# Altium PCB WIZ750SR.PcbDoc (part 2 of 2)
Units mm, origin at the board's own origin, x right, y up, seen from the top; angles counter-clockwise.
Board outline 45 x 30 mm, 4 copper layers (Top Layer, Internal Plane 1, Internal Plane 2, Bottom Layer); 93 components, 69 nets, 325 pads, 127 vias.
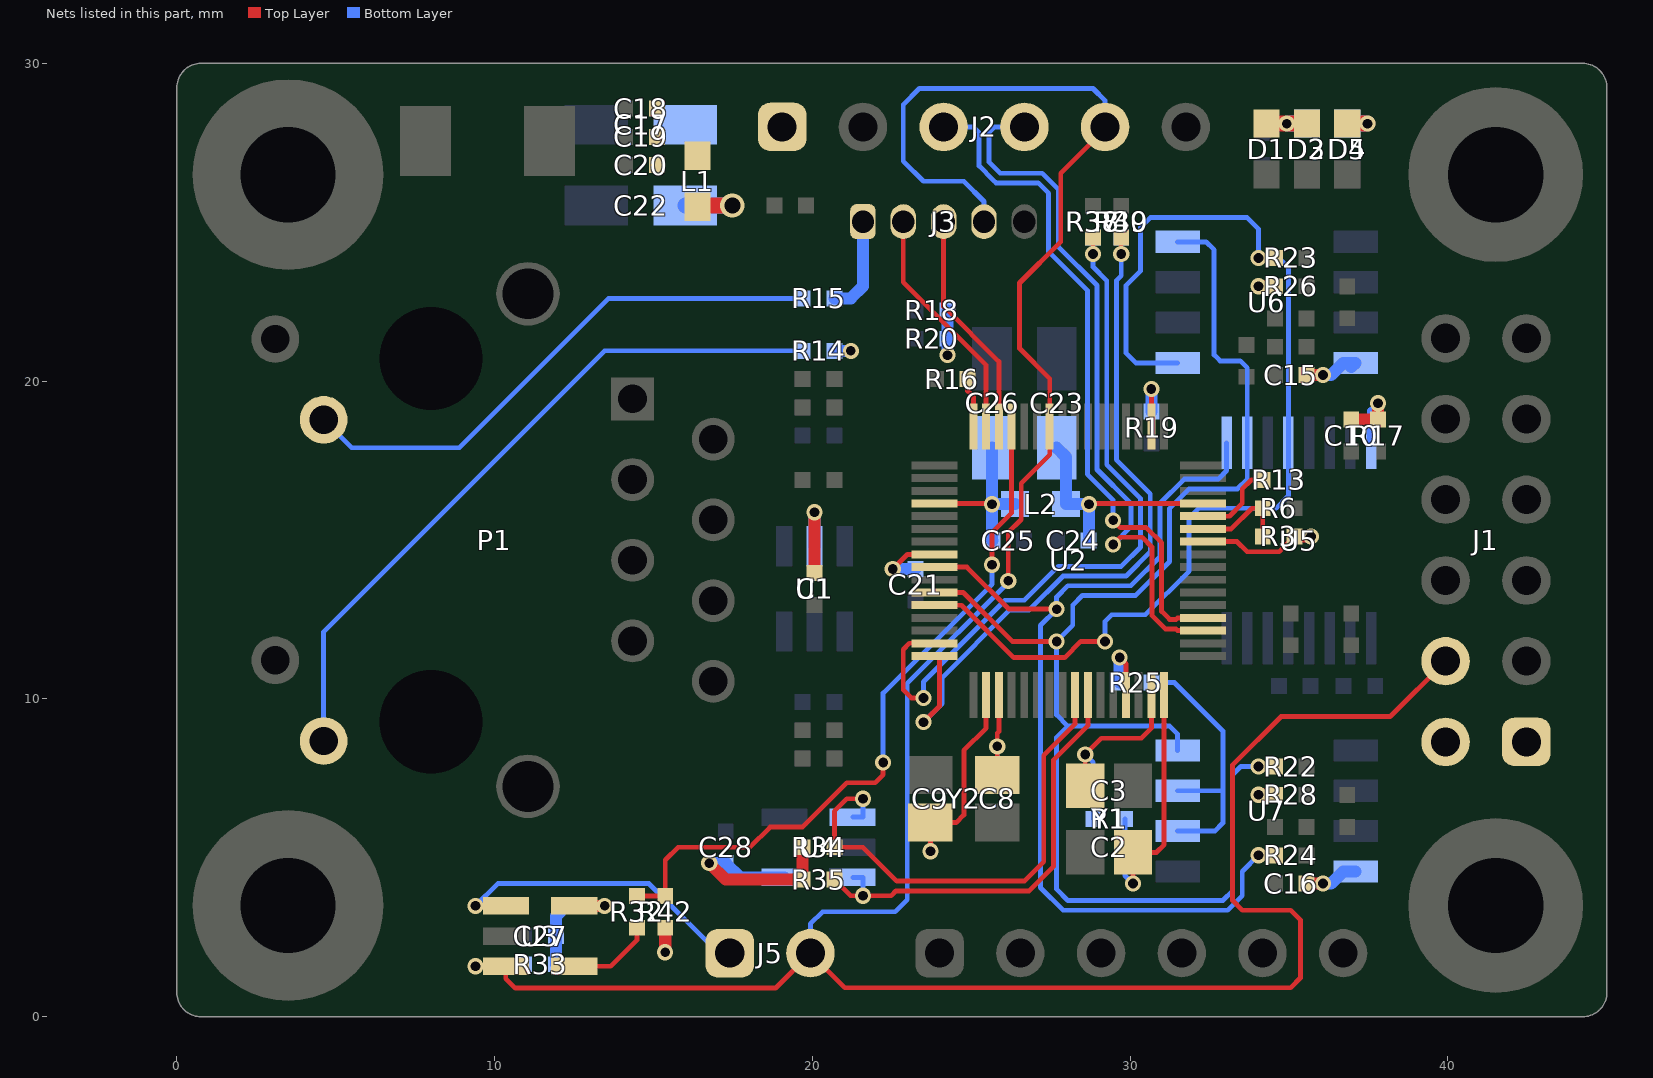
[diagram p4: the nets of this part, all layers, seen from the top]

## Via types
v1: diameter 0.508, hole 0.305, Top Layer to Bottom Layer, tented both sides, 92 vias
v2: diameter 0.762, hole 0.508, Top Layer to Bottom Layer, tented both sides, 35 vias

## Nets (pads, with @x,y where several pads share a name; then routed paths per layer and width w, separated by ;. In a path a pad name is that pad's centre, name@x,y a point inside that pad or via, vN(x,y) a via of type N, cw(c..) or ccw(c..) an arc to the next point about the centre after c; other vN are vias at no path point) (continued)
NetJ5_1: J5.1 U3.1 | length 10.2
  Top Layer w0.152: v1(9.398,3.49) U3.1@10.355,3.49
  Bottom Layer w0.152: v1(9.398,3.49) 10.099,4.191 14.224,4.191 14.859,4.191 17.05,2 J5.1@17.399,2
NetP1_L1: P1.L1 R14.2 | length 22.2
  Bottom Layer w0.152: P1.L1@4.62,8.675 4.62,12.113 13.462,20.955 R14.2@19.693,20.955
NetP1_L3: P1.L3 R15.2 | length 17.4
  Bottom Layer w0.152: P1.L3@4.62,18.785 5.498,17.907 8.89,17.907 13.589,22.606 R15.2@19.693,22.606
NetR13_2: R13.2 U2.12 | length 2.6
  Top Layer w0.152: U2.12@32.292,15.751 33.125,15.751 33.528,16.154 33.528,16.612 33.807,16.891 R13.2@34.171,16.891
NetR16_2: R16.2 U2.32 | length 1.6
  Top Layer w0.152: R16.2@24.884,20.066 24.884,19.693 25.067,19.51 U2.32@25.067,18.576
NetR25_1: R25.1 U7.2 U7.3 | length 8.7
  Bottom Layer w0.152: R25.1@30.675,10.516 31.394,10.516 32.918,8.992 32.918,7.112 ; U7.2@31.49,5.842 32.664,5.842 32.918,6.096 32.918,7.112 ; U7.3@31.49,7.112 32.918,7.112
NetR32_2: R32.2 U3.4 | length 2.9
  Top Layer w0.152: U3.4@12.645,1.45 U3.4@12.505,1.59 13.655,1.59 14.478,2.413 R32.2@14.478,2.802
REGIN: C23.1 C24.2 L2.1 U2.13 | length 7.4
  Top Layer w0.152: v1(28.702,16.129) 28.702,16.151 U2.13@32.292,16.151
  Bottom Layer w0.381: C23.1@27.686,17.904 27.978,17.612 L2.1@27.978,16.129 v1(28.702,16.129) 28.702,14.994 C24.2@28.694,14.986
REGOUT: C25.2 C26.1 L2.2 U2.36 | length 5.5
  Top Layer w0.152: U2.36@23.842,16.151 25.632,16.151 v1(25.654,16.129)
  Bottom Layer w0.381: C26.1@25.654,17.904 v1(25.654,16.129) ; C25.2@25.662,14.986 25.654,14.994 v1(25.654,16.129) ; L2.2@26.378,16.129 v1(25.654,16.129)
"RS232/485 SELECT PIN": R3.1 R6.2 U2.11 | length 3
  Top Layer w0.152: U2.11@32.292,15.351 33.182,15.351 33.833,16.002 R6.2@34.171,16.002 R3.1@34.171,15.113
RSTN: J1.4 J2.5 J3.4 J5.2 R33.1 U2.26 U3.3 | length 90.6
  Top Layer w0.152: v1(9.398,1.59) U3.3@10.355,1.59 10.35,1.585 10.35,1.2 10.65,0.9 18.839,0.9 J5.2@19.939,2 21.025,0.914 35.052,0.914 35.357,1.219 35.357,3.048 35.052,3.353 33.528,3.353 33.223,3.658 33.223,7.925 34.747,9.449 38.185,9.449 J1.4@39.926,11.19 ; v1(26.162,13.716) 26.162,15.24 26.569,15.647 26.569,16.79 27.467,17.688 U2.26@27.467,18.576 27.467,20.082 26.518,21.031 26.518,23.089 27.813,24.384 27.813,26.543 29.21,27.94 J2.5@29.21,28
  Bottom Layer w0.152: v1(9.398,1.59) 10.869,1.59 R33.1@10.93,1.651 ; J5.2@19.939,2 19.939,2.921 20.32,3.302 22.606,3.302 22.987,3.683 22.987,10.49 26.162,13.665 v1(26.162,13.716) ; J3.4@25.4,25.019 25.4,25.654 24.765,26.289 23.495,26.289 22.86,26.924 22.86,28.702 23.368,29.21 28.829,29.21 29.21,28.829 J2.5@29.21,28
RXD_RO: R23.2 U2.44 U5.12 U6.1 | length 34.8
  Top Layer w0.152: U2.44@23.842,12.951 24.692,12.951 26.34,11.303 27.94,11.303 28.448,11.811 v1(29.21,11.811) ; v1(34.036,23.876) R23.2@34.552,23.876
  Bottom Layer w0.152: v1(29.21,11.811) 29.21,12.446 29.413,12.649 30.48,12.649 31.852,14.021 31.852,15.697 32.156,16.002 34.595,16.002 34.981,16.388 U5.12@34.981,18.06 34.981,23.566 34.671,23.876 v1(34.036,23.876) 34.036,24.79 33.68,25.146 30.632,25.146 30.328,24.841 30.328,23.47 29.87,23.012 29.87,20.879 30.175,20.574 U6.1@31.49,20.574
SCL1: R34.1 U2.57 U4.1 | length 16
  Top Layer w0.152: v1(21.59,6.858) 21.082,6.858 20.693,6.469 R34.1@20.693,5.334 21.59,5.334 22.657,4.267 26.67,4.267 27.28,4.877 27.28,8.23 28.267,9.217 U2.57@28.267,10.126
  Bottom Layer w0.152: U4.1@21.268,6.284 21.59,6.284 v1(21.59,6.858)
SDA1: R35.1 U2.58 U4.3 | length 14.3
  Top Layer w0.152: R35.1@20.759,4.384 R35.1@20.693,4.318 21.201,3.81 v1(21.59,3.81) 22.479,3.81 22.631,3.962 26.822,3.962 27.584,4.724 27.584,8.077 28.667,9.16 U2.58@28.667,10.126
  Bottom Layer w0.152: U4.3@21.268,4.384 21.59,4.384 v1(21.59,3.81)
STATUS_LED0: R37.2 R38.2 U2.47 | length 23
  Top Layer w0.152: v1(23.495,10.033) 23.114,10.033 22.86,10.287 22.86,11.557 23.054,11.751 U2.47@23.842,11.751 ; v1(28.829,24.003) R37.2@28.829,24.519
  Bottom Layer w0.152: v1(23.495,10.033) 23.495,10.541 26.06,13.106 26.67,13.106 27.737,14.173 29.718,14.173 30.328,14.783 30.328,16.307 29.261,17.374 29.261,23.165 28.829,23.597 v1(28.829,24.003) R38.2@28.829,24.519
STATUS_LED1: R39.2 R40.2 U2.48 | length 23.2
  Top Layer w0.152: v1(23.495,9.271) 24.003,9.779 24.003,11.351 U2.48@23.842,11.351 ; v1(29.718,24.003) R39.2@29.718,24.519
  Bottom Layer w0.152: v1(23.495,9.271) 24.079,9.855 24.079,10.668 26.213,12.802 26.822,12.802 27.889,13.868 29.87,13.868 30.632,14.63 30.632,16.459 29.566,17.526 29.566,23.165 29.718,23.317 v1(29.718,24.003) R40.2@29.718,24.519
SWCLK: J3.3 U2.30 | length 7.2
  Top Layer w0.152: J3.3@24.13,25.019 24.13,22.352 25.867,20.615 U2.30@25.867,18.576
SWDIO: J3.2 U2.31 | length 7.5
  Top Layer w0.152: J3.2@22.86,25.019 22.86,23.114 25.467,20.507 U2.31@25.467,18.576
TXD_DI: R22.2 U2.43 U5.10 U6.4 U7.4 | length 46.3
  Top Layer w0.152: U2.43@23.842,13.351 24.749,13.351 26.289,11.811 v1(27.686,11.811) ; v1(34.036,7.874) R22.2@34.552,7.874
  Bottom Layer w0.152: U7.4@31.49,8.382 31.49,8.896 31.242,9.144 28.042,9.144 ; U6.4@31.49,24.384 32.385,24.384 32.639,24.13 32.639,20.828 32.829,20.637 33.465,20.637 33.681,20.421 U5.10@33.681,18.06 33.681,16.917 33.376,16.612 31.852,16.612 31.242,16.002 31.242,14.326 30.175,13.259 28.499,13.259 28.194,12.954 28.194,12.319 v1(27.686,11.811) 27.686,9.5 28.042,9.144 ; v1(34.036,7.874) 33.477,7.874 33.223,7.62 33.223,3.962 32.918,3.658 28.042,3.658 27.686,4.013 27.686,8.788 28.042,9.144
U_CTS0: R24.2 U2.41 U5.9 | length 31.4
  Top Layer w0.152: U2.41@23.842,14.151 24.863,14.151 26.187,12.827 v1(27.686,12.827) ; v1(34.036,5.08) R24.2@34.552,5.08
  Bottom Layer w0.152: U5.9@33.031,18.06 33.031,17.181 32.766,16.916 31.699,16.916 30.937,16.154 30.937,14.478 30.023,13.564 28.042,13.564 27.686,13.208 v1(27.686,12.827) 27.178,12.319 27.178,4.064 27.889,3.353 33.071,3.353 33.528,3.81 33.528,4.572 v1(34.036,5.08)
U_RXD2: J2.3 U2.4 | length 21.3
  Top Layer w0.152: v1(29.464,15.621) 29.693,15.392 30.505,15.392 30.988,14.909 30.988,12.757 31.242,12.503 31.443,12.503 31.491,12.551 U2.4@32.292,12.551
  Bottom Layer w0.152: J2.3@24.13,28 25.061,28 25.248,27.813 25.248,26.772 25.692,26.327 25.782,26.238 27.102,26.238 27.432,25.908 27.432,24.079 28.651,22.86 28.651,17.069 29.464,16.256 v1(29.464,15.621)
U_TXD2: J2.4 U2.3 | length 22.4
  Top Layer w0.152: v1(29.464,14.859) 29.693,15.088 30.378,15.088 30.683,14.783 30.683,12.631 31.116,12.199 31.443,12.199 31.491,12.151 U2.3@32.292,12.151
  Bottom Layer w0.152: J2.4@26.67,28 25.739,28 25.552,27.813 25.552,26.899 25.908,26.543 27.228,26.543 27.737,26.034 27.737,24.232 28.956,23.012 28.956,17.221 30.023,16.154 30.023,15.418 v1(29.464,14.859)
VDD_3.3A: C21.2 C22.1 L1.2 U2.40 | length 4.8
  Top Layer w0.152: v1(22.53,14.089) 22.992,14.551 U2.40@23.842,14.551
  Top Layer w0.508: L1.2@16.383,25.489 16.421,25.527 v2(17.481,25.527)
  Bottom Layer w0.381: v1(22.53,14.089) C21.2@23.241,14.089
  Bottom Layer w0.508: C22.1@16.005,25.527 v2(17.481,25.527)
VDD_3.3V: C1.2 C10.2 C15.2 C16.2 C17.1 C18.2 C19.2 C20.2 C27.2 C28.2 D1.1 D2.1 D3.1 D4.1 D5.1 J1.1 J1.2 J2.1 J3.1 L1.1 R3.2 R14.1 R15.1 R17.1 R18.2 R19.2 R20.2 R25.2 R26.1 R28.1 R33.2 R34.2 R35.2 R42.1 U1.5 U2.10 U2.18 U2.61 U3.5 U4.4 U5.16 U6.8 U7.8 | length 37.4
  Top Layer w0.152: v1(29.667,11.303) 29.867,11.103 U2.61@29.867,10.126 ; U2.18@30.667,18.576 v1(30.667,19.753) ; U2.10@32.292,14.951 33.36,14.951 33.68,14.63 34.688,14.63 R3.2@35.171,15.113
  Top Layer w0.381: U3.5@12.505,3.49 v1(13.462,3.49) ; v1(15.367,2.032) 15.371,2.036 R42.1@15.371,2.802 ; v1(16.756,4.834) 17.272,4.318 R35.2@19.693,4.318 R34.2@19.693,5.334 ; C1.2@20.066,13.962 v1(20.066,15.875) ; v1(34.036,6.985) R28.1@34.552,6.985 ; v1(34.036,22.987) R26.1@34.552,22.987 ; R3.2@35.171,15.113 v1(35.687,15.113) ; C16.2@35.552,4.191 v1(36.068,4.191) ; C15.2@35.552,20.193 v1(36.068,20.193) ; C10.2@36.957,18.788 R17.1@37.795,18.788 v1(37.795,19.304)
  Top Layer w0.508: D1.1@34.29,28.105 v1(34.925,28.105) D2.1@35.56,28.105 ; D4.1@36.83,28.105 v1(37.465,28.105)
  Bottom Layer w0.254: U5.16@37.581,18.06 37.581,19.061
  Bottom Layer w0.381: R33.2@11.93,1.651 C27.2@11.93,2.54 11.93,3.167 12.253,3.49 v1(13.462,3.49) ; v1(16.756,4.834) C28.2@17.272,4.834 17.722,4.384 U4.4@19.118,4.384 ; U1.5@20.066,14.802 v1(20.066,15.875) ; R14.1@20.693,20.955 v1(21.209,20.955) ; R15.1@20.693,22.606 21.209,22.606 21.59,22.987 J3.1@21.59,25.019 ; v1(24.249,20.82) R20.2@24.249,21.336 R18.2@24.249,22.225 ; R25.2@29.667,10.524 v1(29.667,11.303) ; R19.2@30.67,19.042 v1@30.67,19.75 ; v1(36.068,4.191) 36.322,4.191 36.703,4.572 U7.8@37.09,4.572 ; v1(36.068,20.193) 36.322,20.193 36.703,20.574 U6.8@37.09,20.574 U6.8@36.957,20.441
  Bottom Layer w0.508: v1(34.925,28.105) D3.1@35.56,28.105 ; D5.1@36.83,28.105 v1(37.465,28.105)
WDI: R32.1 R42.2 U2.29 | length 22.6
  Top Layer w0.152: R32.1@14.478,3.802 R42.2@15.371,3.802 15.371,4.933 15.772,5.334 18.034,5.334 18.669,5.969 19.685,5.969 21.082,7.366 21.971,7.366 22.225,7.62 v1(22.225,8.001) ; v1(25.654,14.224) 25.654,15.24 26.267,15.853 U2.29@26.267,18.576
  Bottom Layer w0.152: v1(22.225,8.001) 22.225,10.185 25.654,13.614 v1(25.654,14.224)
X1: C9.2 U2.50 Y2.3 | length 7.3
  Top Layer w0.152: v1(23.715,5.207) Y2.3@23.715,6.108 24.523,6.108 24.765,6.35 24.765,8.382 25.467,9.084 U2.50@25.467,10.126
  Bottom Layer w0.152: v1(23.715,5.207) C9.2@23.715,6.358
X2: C8.2 U2.51 Y2.1 | length 3.7
  Top Layer w0.152: Y2.1@25.815,7.608 v1(25.815,8.509) 25.815,8.924 25.867,8.976 U2.51@25.867,10.126
  Bottom Layer w0.152: C8.2@25.815,7.358 v1(25.815,8.509)
XIN: C3.2 R1.2 U2.63 Y1.3 | length 6.6
  Top Layer w0.152: Y1.3@28.587,7.273 v1(28.587,8.255) 29.095,8.763 30.353,8.763 30.667,9.077 U2.63@30.667,10.126
  Bottom Layer w0.152: v1(28.587,8.255) 28.837,8.005 C3.2@28.837,7.112 R1.2@28.837,6.223
XOUT: C2.2 R1.1 U2.64 Y1.1 | length 8.9
  Top Layer w0.152: v1(30.087,4.191) Y1.1@30.087,5.173 30.827,5.173 31.067,5.413 U2.64@31.067,10.126
  Bottom Layer w0.152: R1.1@29.837,6.223 C2.2@29.837,5.334 29.837,4.441 v1(30.087,4.191)
pads on no net: P1. P1.R4 P1.R5 P1.R6 U2.8 U2.19 U2.20 U2.21 U2.22 U2.27 U2.45 U2.46 U2.53 U2.54 U2.55 U2.56 U2.59 U2.60 U7.1
copper on no net:
  other v2: 41.5,1.417 40.027,2.027 42.973,2.027 39.417,3.5 43.583,3.5 40.027,4.973 42.973,4.973 41.5,5.583 41.5,24.417 40.027,25.027 42.973,25.027 39.417,26.5 43.583,26.5 40.027,27.973 42.973,27.973 41.5,28.583

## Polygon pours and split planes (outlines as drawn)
VDD_3.3V on Top Layer "Top Layer-net" (solid, remove dead copper, pour order 2): 14.859,26.543 19.812,26.543 20.066,26.797 20.066,29.21 19.812,29.464 19.05,29.464 15.113,29.464 14.859,29.21 14.859,26.543
CH_GND on Top Layer "Top Layer-net" (solid, remove dead copper, pour order 12): 0.762,29.591 0.381,29.21 0.381,27.432 0.381,0.762 0.762,0.381 2.413,0.381 6.198,0.381 6.604,0.787 6.604,1.143 6.604,5.588 6.985,5.969 8.128,5.969 11.938,5.969 12.192,6.223 12.192,23.749 11.938,24.003 9.017,24.003 8.636,24.384 8.636,29.058 8.103,29.591
GND on Top Layer "Top Layer-gnd" (solid, remove dead copper, pour order 16): 11.176,29.591 10.922,29.337 10.922,28.448 10.922,25.527 11.176,25.273 11.811,25.273 12.827,25.273 13.462,24.638 14.605,23.495 18.288,23.495 19.177,23.495 19.431,23.241 19.431,22.987 19.431,6.731 19.177,6.477 18.415,6.477 14.605,6.477 12.954,4.826 8.763,4.826 8.509,4.572 8.509,4.318 8.509,0.635 8.763,0.381 9.652,0.381 37.211,0.381 37.465,0.635 37.465,0.889 37.465,5.461 39.243,7.239 39.624,7.62 42.799,7.62 44.323,7.62 44.577,7.874 44.577,8.509 44.577,22.098 44.323,22.352 44.069,22.352 39.624,22.352 37.465,24.511 37.465,28.575 37.465,29.337 37.211,29.591
GND on Bottom Layer "Top Layer-gnd" (solid, remove dead copper, pour order 22): 11.049,29.464 10.922,29.337 10.922,28.448 10.922,25.527 11.176,25.273 11.811,25.273 12.827,25.273 13.462,24.638 14.605,23.495 18.288,23.495 19.177,23.495 19.431,23.241 19.431,22.987 19.431,6.731 19.177,6.477 18.415,6.477 14.605,6.477 12.827,4.699 8.636,4.699 8.509,4.572 8.509,4.318 8.509,0.635 8.763,0.381 9.652,0.381 37.211,0.381 37.465,0.635 37.465,0.889 37.465,5.461 39.243,7.239 39.624,7.62 42.799,7.62 44.323,7.62 44.577,7.874 44.577,8.509 44.577,22.098 44.323,22.352 44.069,22.352 39.624,22.352 37.465,24.511 37.465,28.575 37.465,29.337 37.338,29.464
CH_GND on Bottom Layer "Top Layer-net" (solid, remove dead copper, pour order 20): 0.762,29.591 0.381,29.21 0.381,27.432 0.381,0.762 0.762,0.381 2.413,0.381 6.198,0.381 6.604,0.787 6.604,1.143 6.604,5.588 6.985,5.969 8.128,5.969 11.938,5.969 12.192,6.223 12.192,23.749 11.938,24.003 9.017,24.003 8.636,24.384 8.636,29.058 8.103,29.591
VDD_3.3V on Bottom Layer "Top Layer-net" (solid, remove dead copper, pour order 6): 16.256,28.829 15.113,28.829 14.859,28.575 14.859,27.559 14.859,27.305 15.113,27.051 16.002,27.051 19.812,27.051 20.066,27.305 20.066,28.575 19.812,28.829
GND on Internal Plane 1 (split plane): 44.304,29.483 44.365,29.458 44.417,29.417 44.458,29.365 44.483,29.304 44.49,29.247 44.49,29.238 44.49,24.044 44.133,23.687 40.212,23.687 38.673,25.226 38.673,29.207 38.956,29.49 44.238,29.49 44.247,29.49
CH_GND on Internal Plane 1 (split plane): 44.49,6.157 44.49,0.762 44.49,0.753 44.483,0.696 44.458,0.635 44.417,0.583 44.365,0.542 44.304,0.517 44.247,0.51 44.238,0.51 38.953,0.51 38.673,0.791 38.673,4.746 40.339,6.412 44.235,6.412
GND on Internal Plane 1 (split plane): 38.289,29.209 38.289,25.146 38.295,25.096 38.307,25.069 38.315,25.05 38.345,25.01 39.996,23.359 40.036,23.329 40.082,23.309 40.132,23.303 44.133,23.303 44.49,22.946 44.49,7.051 44.235,6.796 40.259,6.796 40.209,6.79 40.163,6.77 40.123,6.74 38.345,4.962 38.315,4.922 38.307,4.903 38.295,4.876 38.289,4.826 38.289,0.889 38.289,0.791 38.009,0.51 8.56,0.51 8.56,4.496 8.738,4.674 12.802,4.674 14.173,6.045 14.605,6.477 18.745,6.477 18.745,22.86 15.215,22.86 12.802,25.273 12.273,25.273 11.125,25.273 10.82,25.578 10.82,29.489 9.441,29.489 9.441,29.49 38.009,29.49
CH_GND on Internal Plane 1 (split plane): 0.762,29.49 8.341,29.49 8.558,29.273 8.636,29.195 8.636,25.527 8.637,25.273 8.636,24.383 9.017,24.003 11.938,24.003 12.192,23.749 12.191,6.298 11.862,5.969 6.909,5.969 6.553,5.613 6.553,0.678 6.386,0.51 0.762,0.51 0.753,0.51 0.696,0.517 0.635,0.542 0.583,0.583 0.542,0.635 0.517,0.696 0.51,0.753 0.51,0.762 0.51,29.238 0.51,29.247 0.517,29.304 0.542,29.365 0.583,29.417 0.635,29.458 0.696,29.483 0.753,29.49
VDD_3.3V on Internal Plane 2 (split plane): 44.304,29.483 44.365,29.458 44.417,29.417 44.458,29.365 44.483,29.304 44.49,29.247 44.49,29.238 44.49,24.035 44.142,23.687 40.212,23.687 38.673,25.226 38.673,29.209 38.953,29.49 44.238,29.49 44.247,29.49
VDD_3.3A on Internal Plane 2 (split plane): 14.489,29.311 14.489,26.645 14.496,26.595 14.507,26.568 14.515,26.549 14.545,26.509 14.825,26.229 14.865,26.199 14.911,26.18 14.961,26.173 20.237,26.173 20.509,25.901 20.509,17.174 20.418,17.083 19.939,17.083 19.889,17.077 19.843,17.057 19.803,17.027 19.549,16.773 19.519,16.733 19.511,16.714 19.499,16.687 19.493,16.637 19.493,15.037 19.499,14.987 19.511,14.96 19.519,14.941 19.549,14.901 19.854,14.596 19.894,14.566 19.913,14.558 19.94,14.546 19.99,14.54 23.034,14.54 23.176,14.398 23.176,12.754 23.06,12.638 18.72,12.638 18.72,18.009 19.406,18.009 19.406,20.345 18.72,20.345 18.72,22.835 15.24,22.835 12.802,25.273 12.273,25.273 11.125,25.273 10.82,25.578 10.82,29.489 9.441,29.489 9.441,29.49 14.31,29.49
CH_GND on Internal Plane 2 (split plane): 44.49,6.14 44.49,0.762 44.49,0.753 44.483,0.696 44.458,0.635 44.417,0.583 44.365,0.542 44.304,0.517 44.247,0.51 44.238,0.51 38.953,0.51 38.673,0.791 38.673,4.746 40.339,6.412 44.218,6.412
VDD_3.3V on Internal Plane 2 (split plane): 38.289,29.207 38.289,25.146 38.295,25.096 38.307,25.069 38.315,25.05 38.345,25.01 39.996,23.359 40.036,23.329 40.082,23.309 40.132,23.303 44.133,23.303 44.49,22.946 44.49,7.051 44.235,6.796 40.259,6.796 40.209,6.79 40.163,6.77 40.123,6.74 38.345,4.962 38.315,4.922 38.307,4.903 38.295,4.876 38.289,4.826 38.289,0.791 38.009,0.51 8.56,0.51 8.56,4.496 8.738,4.674 12.802,4.674 14.173,6.045 14.605,6.477 18.72,6.477 18.72,12.254 23.139,12.254 23.189,12.26 23.216,12.272 23.235,12.28 23.275,12.31 23.504,12.539 23.534,12.579 23.554,12.625 23.56,12.675 23.56,14.478 23.554,14.528 23.534,14.574 23.504,14.614 23.25,14.868 23.21,14.898 23.191,14.906 23.164,14.918 23.114,14.924 20.069,14.924 19.877,15.116 19.877,16.557 20.019,16.699 20.498,16.699 20.548,16.705 20.575,16.717 20.594,16.725 20.634,16.755 20.837,16.958 20.867,16.998 20.887,17.044 20.893,17.094 20.893,25.981 20.887,26.031 20.875,26.058 20.867,26.077 20.837,26.117 20.453,26.501 20.413,26.532 20.394,26.54 20.366,26.551 20.317,26.557 15.04,26.557 14.873,26.724 14.873,29.308 15.055,29.49 38.006,29.49
CH_GND on Internal Plane 2 (split plane): 0.762,29.49 8.341,29.49 8.509,29.322 8.636,29.195 8.636,25.527 8.637,25.273 8.636,24.383 9.017,24.003 11.938,24.003 12.192,23.749 12.191,6.298 11.862,5.969 6.909,5.969 6.553,5.613 6.553,0.678 6.386,0.51 0.762,0.51 0.753,0.51 0.696,0.517 0.635,0.542 0.583,0.583 0.542,0.635 0.517,0.696 0.51,0.753 0.51,0.762 0.51,29.238 0.51,29.247 0.517,29.304 0.542,29.365 0.583,29.417 0.635,29.458 0.696,29.483 0.753,29.49

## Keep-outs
Keep-Out Layer:
  the board outline again, w0.127
  text ".Layer_Name" at 9.398,31.75 h1.52

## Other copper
Top Layer:
  pour cut-out: 42.164,12.141 42.164,12.725 42.367,12.725 42.367,12.141
  pour cut-out: 40.843,13.31 41.097,13.564 41.3,13.564 41.554,13.31 41.554,14.173 40.843,14.173
  pour cut-out: 12.191,6.298 12.192,23.749 11.938,24.003 9.017,24.003 8.636,24.383 8.637,25.273 8.636,25.527 8.636,29.489 10.82,29.489 10.82,25.578 11.125,25.273 12.273,25.273 12.802,25.273 15.215,22.86 18.745,22.86 18.745,6.477 14.605,6.477 14.173,6.045 12.802,4.674 8.738,4.674 8.56,4.496 8.56,0.483 6.553,0.483 6.553,5.613 6.909,5.969 11.862,5.969
  pour cut-out: 14.63,29.206 14.122,29.206 14.227,29.31 14.227,29.461 13.997,29.691 13.741,29.691 13.741,30 14.63,30
  pour cut-out: 18.161,6.477 18.39,6.477 18.39,6.121 18.161,6.121 18.263,6.223 18.263,6.375
  pour cut-out: 10.033,1.016 10.312,1.016 10.312,0.381 10.033,0.381 10.033,0.432 10.109,0.508 10.109,0.711 10.033,0.787
  pour cut-out: 14.681,4.394 14.935,4.648 14.935,4.394
  pour cut-out: 22.784,17.475 22.631,17.628 22.784,17.628
  pour cut-out: 21.272,18.567 21.45,18.567 21.806,18.567 21.806,18.237 21.667,18.237 21.632,18.272 21.632,18.449 21.552,18.53 21.32,18.53
  pour cut-out: 21.996,8.966 22.225,8.966 22.327,8.865 22.708,8.865 22.809,8.966 22.809,9.677 22.657,9.83 22.809,9.83 23.05,9.83 23.05,9.207 23.393,8.865 23.393,8.458 21.996,8.458
  text ".Layer_Name" at 9.398,31.75 h1.52
Bottom Layer:
  pour cut-out: 22.047,16.358 22.098,16.358 22.327,16.586 21.869,17.221 21.717,17.069 21.361,17.069
  pour cut-out: 24.181,13.056 24.181,16.866 23.444,17.602 23.444,18.339 23.216,18.11 23.012,18.11 22.835,18.288 22.835,18.009 22.835,17.45 23.698,16.586 23.673,16.561 23.673,15.545 22.962,14.834 22.962,14.63 23.825,14.63 23.825,13.056
  pour cut-out: 12.191,6.298 12.192,23.749 11.938,24.003 9.017,24.003 8.636,24.383 8.637,25.273 8.636,25.527 8.636,29.489 10.82,29.489 10.82,25.578 11.125,25.273 12.273,25.273 12.802,25.273 15.215,22.86 18.745,22.86 18.745,6.477 14.605,6.477 14.173,6.045 12.802,4.674 8.738,4.674 8.56,4.496 8.56,0.483 6.553,0.483 6.553,5.613 6.909,5.969 11.862,5.969
  pour cut-out: 21.692,20.371 22.098,20.371 21.869,20.599 21.869,20.752 21.869,20.98 22.073,21.184 21.692,21.184
  pour cut-out: 22.504,21.158 22.657,21.006 22.657,21.158
  pour cut-out: 32.537,17.526 32.334,17.323 32.537,17.323
  pour cut-out: 33.267,19.402 33.064,19.199 33.267,19.199
  text ".Layer_Name" at 9.398,31.75 h1.52
Internal Plane 1 (plane layer: these items are gaps in the copper):
  pour cut-out: 12.191,6.298 12.192,23.749 11.938,24.003 9.017,24.003 8.636,24.383 8.637,25.273 8.636,25.527 8.636,29.489 10.82,29.489 10.82,25.578 11.125,25.273 12.273,25.273 12.802,25.273 15.215,22.86 18.745,22.86 18.745,6.477 14.605,6.477 14.173,6.045 12.802,4.674 8.738,4.674 8.56,4.496 8.56,0.483 6.553,0.483 6.553,5.613 6.909,5.969 11.862,5.969
  lines w0.381: 6.147,0 6.833,0.686 6.858,0.686 ; 7.544,0 6.858,0.686 ; 8.103,29.997 8.105,29.997 8.301,29.801 8.694,29.409 8.89,29.213 ; 8.891,29.483 9.163,29.483 ; 9.68,30 8.89,29.21 8.89,24.638 9.271,24.257 12.04,24.257 12.446,23.851 12.446,6.096 12.065,5.715 7.214,5.715 6.858,5.359 6.858,0.686 ; 37.77,0 38.481,0.711 ; 37.821,30 37.821,29.949 38.481,29.289 38.481,29.314 ; 38.481,0 38.481,0.889 ; 39.192,0 38.481,0.711 ; 39.192,29.997 38.481,29.286 38.481,25.146 40.132,23.495 44.213,23.495 ; 45,6.604 44.314,6.604 ; 45,7.29 44.314,6.604 ; 45,22.708 44.213,23.495 ; 45,23.495 44.213,23.495 ; 45,24.282 44.213,23.495 ; 45.004,5.914 44.314,6.604 ; 38.481,0.711 38.481,4.826 40.259,6.604 44.314,6.604
  text "GND" at 9.398,31.782 h1.52
Internal Plane 2 (plane layer: these items are gaps in the copper):
  pour cut-out: 18.694,18.009 19.406,18.009 19.406,20.345 18.694,20.345
  pour cut-out: 12.191,6.298 12.192,23.749 11.938,24.003 9.017,24.003 8.636,24.383 8.637,25.273 8.636,25.527 8.636,29.489 10.82,29.489 10.82,25.578 11.125,25.273 12.273,25.273 12.802,25.273 15.24,22.835 18.72,22.835 18.72,6.477 14.605,6.477 14.173,6.045 12.802,4.674 8.738,4.674 8.56,4.496 8.56,0.483 6.553,0.483 6.553,5.613 6.909,5.969 11.862,5.969
  lines w0.381: 6.248,0.102 6.833,0.686 6.858,0.686 ; 7.544,0 6.858,0.686 ; 9.169,29.489 9.138,29.458 8.645,29.458 8.103,30 8.89,29.213 ; 14.072,30 14.681,29.39 14.681,29.388 ; 15.596,30 15.293,30 14.681,29.388 ; 18.415,12.446 23.139,12.446 23.368,12.675 23.368,14.478 23.114,14.732 19.99,14.732 19.685,15.037 19.685,16.637 19.939,16.891 20.498,16.891 20.701,17.094 20.701,25.981 20.317,26.365 14.961,26.365 14.681,26.645 14.681,29.388 ; 38.481,0 37.77,0 38.481,0.711 ; 38.481,30.013 38.783,30.013 ; 39.192,0 38.481,0.711 ; 39.192,30 38.481,29.289 38.481,29.286 ; 44.975,23.495 44.221,23.495 ; 45,6.604 45,7.29 44.314,6.604 44.298,6.604 ; 45,22.708 44.213,23.495 ; 45.004,5.897 44.298,6.604 ; 45.004,24.278 44.221,23.495 ; 6.858,0.686 6.858,5.359 7.214,5.715 12.065,5.715 12.446,6.096 12.446,23.851 12.04,24.257 9.271,24.257 8.89,24.638 8.89,29.21 ; 8.89,29.21 9.68,30 37.767,30 38.481,29.286 ; 8.89,29.21 8.89,29.213 ; 8.89,29.21 8.89,29.213 ; 38.481,0.711 38.481,4.826 40.259,6.604 44.298,6.604 ; 38.481,29.286 38.481,25.146 40.132,23.495 44.213,23.495 ; 44.213,23.495 44.221,23.495
  text "POWER" at 9.398,31.782 h1.52

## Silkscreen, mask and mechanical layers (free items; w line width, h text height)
Top Overlay:
  text ".Layer_Name" at 9.398,31.782 h1.52
  text "WIZ750SR Ver1.1" at 6.604,5.334 h1.52
Bottom Overlay:
  lines w0.203: 24.003,2 24.003,3.238 26.67,3.238 ; 28.829,3.238 31.623,3.238 31.623,2
  text ".Layer_Name" at 9.398,31.75 h1.52
  text "VDD" at 19.812,28.956 h0.64
  text "BOOT" at 22.606,28.956 h0.64
  text "RX" at 24.638,28.956 h0.64
  text "TX" at 27.178,28.956 h0.64
  text "nRST" at 30.226,28.956 h0.64
  text "GND" at 32.512,28.956 h0.64
  text "JTAG" at 25.253,25.961 h0.64
  text "GND" at 42.037,19.812 h0.64
  text "485_SEL" at 41.783,17.272 h0.64
  text "CTS" at 43.688,17.272 h0.64
  text "DSR" at 40.64,14.732 h0.64
  text "TXD" at 43.688,14.732 h0.64
  text "WIZ750SR" at 8.382,14.021 h1.52
  text "Ver1.1" at 8.407,12.954 h1.52
  text "DTR" at 40.64,12.192 h0.64
  text "RTS" at 43.688,12.192 h0.64
  text "nRESET" at 41.402,9.652 h0.64
  text "RXD" at 43.688,9.652 h0.64
  text "VDD" at 42.037,6.985 h0.64
  text "GPIO" at 28.639,2.921 h0.64
  text "WDT" at 19.939,0.381 h0.64
  text "D" at 24.194,0.381 h0.64
  text "C" at 26.733,0.381 h0.64
  text "B" at 29.273,0.381 h0.64
  text "A" at 31.813,0.381 h0.64
  text "A_Boot" at 35.56,0.381 h0.64
  text "GND" at 37.529,0.381 h0.64
Top Paste:
  text ".Layer_Name" at 9.398,31.75 h1.52
Bottom Paste:
  text ".Layer_Name" at 9.398,31.75 h1.52
Top Solder:
  text ".Layer_Name" at 9.398,31.75 h1.52
Bottom Solder:
  text ".Layer_Name" at 9.398,31.75 h1.52
Drill Guide:
  text ".Layer_Name" at 9.398,31.75 h1.52
Mechanical 2:
  lines w0.127: 51.892,12.065 78.054,12.065 ; 51.892,14.859 78.054,14.859 ; 0,0.762 ccw(c0.762,0.762) 0.762,0 44.238,0 ccw(c44.238,0.762) 45,0.762 45,29.238 ccw(c44.238,29.238) 44.238,30 0.762,30 ccw(c0.762,29.238) 0,29.238 0,0.762 ; 50.546,0.711 ccw(c51.257,0.711) 51.257,0 78.435,0 ccw(c78.435,0.711) 79.146,0.711 79.146,19.939 ccw(c78.435,19.939) 78.435,20.65 51.257,20.65 ccw(c51.257,19.939) 50.546,19.939 50.546,0.711
  text "BOARD NAME : WIZ750SR" at 0,42.926 h1.52
  text "VERSION : V1.1" at 0,40.132 h1.52
  text "SIZE : 45mmX30mmX1.6T" at 0,37.338 h1.52
  text "GERBER DATE : 2017.07.13" at 0,34.544 h1.52
  text "LAYER :" at 0,31.75 h1.52
  text "Layer Stack Up Detail for:" at 52.019,18.542 h1.02
  text "WIZ750SR V1.1.PcbDoc" at 51.892,16.129 h1.27
  text "Layer Name : 4L  1.6T" at 52.019,12.954 h1.02
  text "Top Layer" at 51.892,9.271 h1.52
  text "GND" at 51.892,6.477 h1.52
  text "POWER" at 51.892,3.81 h1.52
  text "Bottom Layer" at 51.892,1.27 h1.52
  text "KS-TECH artwork" at 50.495,-4.191 h5.08
Drill Drawing:
  text ".Layer_Name" at 9.398,31.75 h1.52
  text ".Legend" at 50.546,22.098 h1.02

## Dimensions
0,0.762 to 45,0.762 on Mechanical 2
0.762,0 to 0.762,30 on Mechanical 2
